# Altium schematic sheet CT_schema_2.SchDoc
size 313 x 200 mm
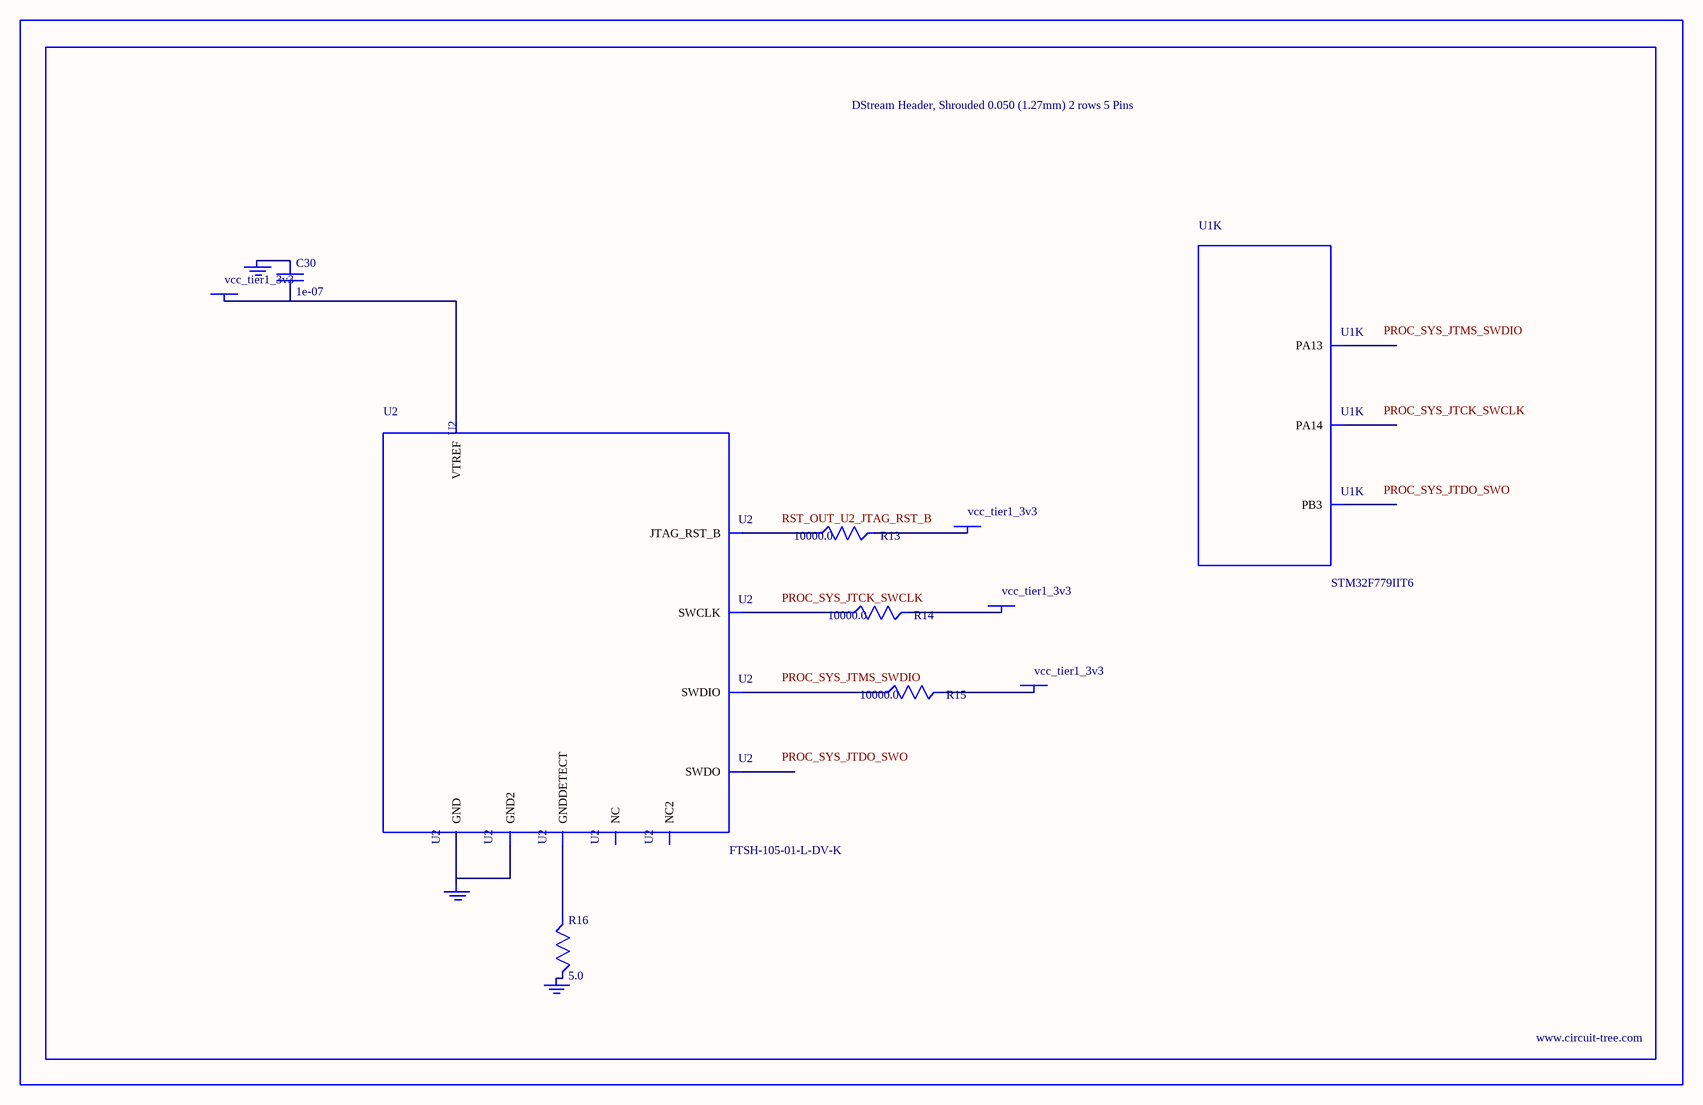
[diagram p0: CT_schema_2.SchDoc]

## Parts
BORDER1  (no value)
C30  1e-07  [C0402]
GND_INSTANCE_1_0  (no value)
GND_INSTANCE_1_1  (no value)
GND_INSTANCE_1_2  (no value)
POWER_INSTANCE_1_0  vcc_tier1_3v3
POWER_INSTANCE_1_1  vcc_tier1_3v3
POWER_INSTANCE_1_2  vcc_tier1_3v3
POWER_INSTANCE_1_3  vcc_tier1_3v3
R13  10000.0  [R0603]
R14  10000.0  [R0603]
R15  10000.0  [R0603]
R16  5.0  [R0603]
U1  STM32F779IIT6  [LQFP176]  (part K of 14)
U2  FTSH-105-01-L-DV-K  [SAMTEC_FTSH-105-01-L-DV-K]

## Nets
NetC30_1: C30.1 GND_INSTANCE_1_0.0(GND)
NetC30_2: C30.2 POWER_INSTANCE_1_0.0(PWR) U2.1(VTREF)
NetGND_INSTANCE_1_1_0: GND_INSTANCE_1_1.0(GND) R16.2
NetGND_INSTANCE_1_2_0: GND_INSTANCE_1_2.0(GND) U2.3(GND) U2.5(GND2)
NetPOWER_INSTANCE_1_1_0: POWER_INSTANCE_1_1.0(PWR) R15.2
NetPOWER_INSTANCE_1_2_0: POWER_INSTANCE_1_2.0(PWR) R14.2
NetPOWER_INSTANCE_1_3_0: POWER_INSTANCE_1_3.0(PWR) R13.2
NetR13_1: R13.1 U2.10(JTAG_RST_B)
NetR14_1: R14.1 U2.4(SWCLK)
NetR15_1: R15.1 U2.2(SWDIO)
NetR16_1: R16.1 U2.9(GNDDETECT)

Not connected (* = marked no-connect by the designer): U1 128(PA13) 137(PA14) 161(PB3); U2 6(SWDO) 7(NC) 8(NC2)

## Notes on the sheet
- Labels drawn without touching a wire or pin: PROC_SYS_JTCK_SWCLK, PROC_SYS_JTDO_SWO, PROC_SYS_JTMS_SWDIO, RST_OUT_U2_JTAG_RST_B

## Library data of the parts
BORDER1 = BORDER_PAGE1
C30 = C0402C104K3RACTU
GND_INSTANCE_1_0-GND_INSTANCE_1_2 = GND
POWER_INSTANCE_1_0-POWER_INSTANCE_1_3 = PWR
R13-R15 = RC0603JR-0710KL
R16 = ERJ-3GEYJ5R1V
